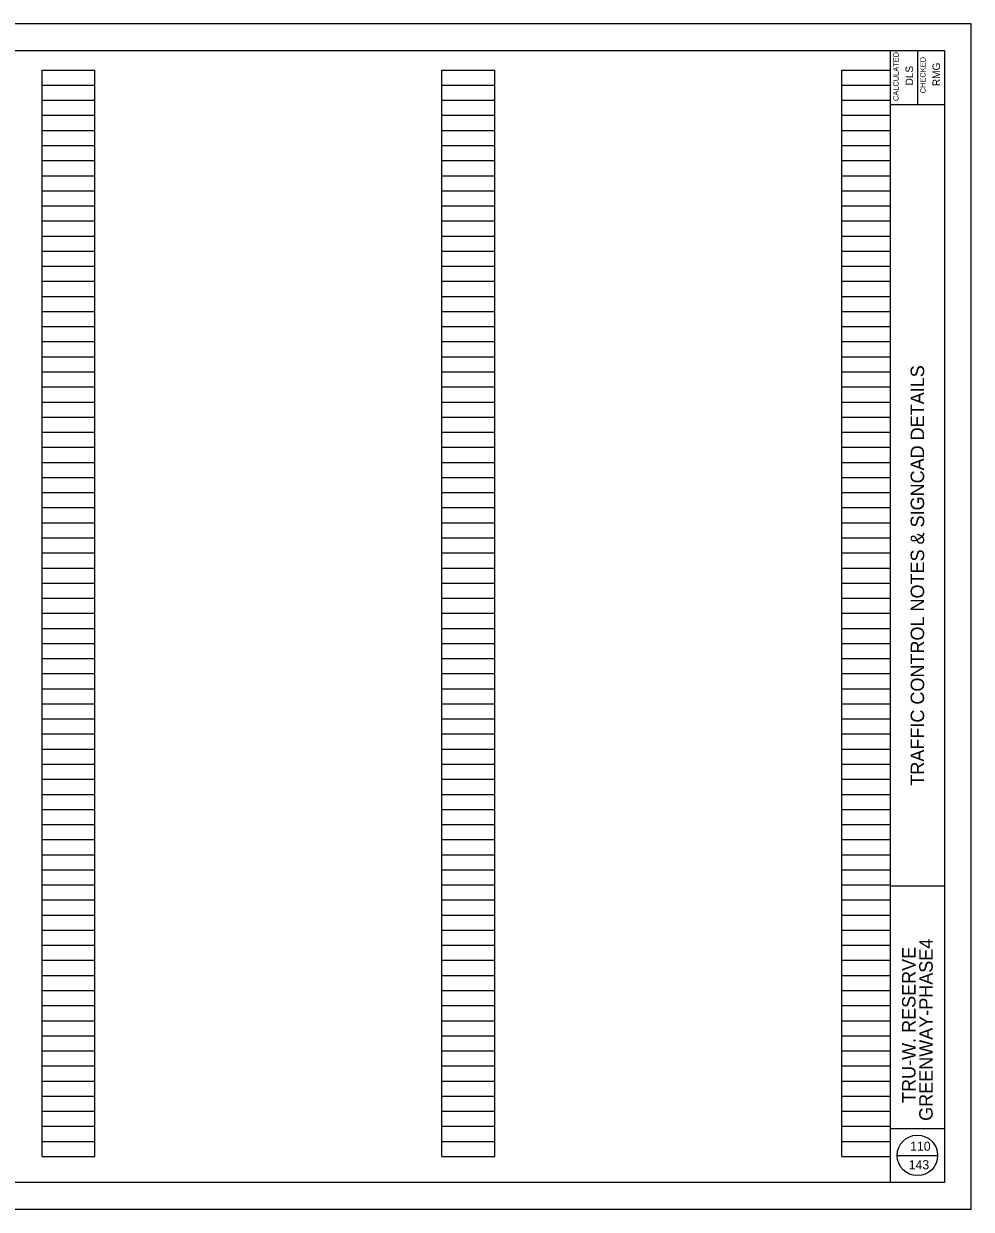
# Model space of a CAD drawing. Extents: x -16.4 to 17.6, y -12.9 to 9.1.
# Drawn here: x 0.05 to 17.63, y -12.91 to 9.09 of the extents above; entities that cross this region are included whole.
import ezdxf

# ---------------------------------------------------------------- set-up
doc = ezdxf.new("R2010")
doc.units = 0
for name, color, linetype in [('SC_Scratch1', 7, 'Continuous'), ('SH_Border', 7, 'Continuous'), ('SH_Cut_Line', 7, 'Continuous'), ('SH_Data', 7, 'Continuous')]:
    doc.layers.add(name, color=color, linetype=linetype)

msp = doc.modelspace()

# ---------------------------------------------------------------- linework, layer by layer
at = {"layer": 'SC_Scratch1'}
for p, q in [((0.389, -11.927), (0.389, 8.233)), ((0.389, 8.233), (1.369, 8.233)), ((1.369, -11.927), (1.369, 8.233)), ((7.809, -11.927), (7.809, 8.233)), ((7.809, 8.233), (8.789, 8.233)), ((8.789, -11.927), (8.789, 8.233)), ((15.229, -11.927), (15.229, 8.233)), ((15.229, 8.233), (16.129, 8.233)), ((16.129, -11.927), (16.129, 8.233)), ((0.389, 7.953), (1.369, 7.953)), ((7.809, 7.953), (8.789, 7.953)), ((15.229, 7.953), (16.129, 7.953)), ((0.389, 7.673), (1.369, 7.673)), ((7.809, 7.673), (8.789, 7.673)), ((15.229, 7.673), (16.129, 7.673)), ((0.389, 7.393), (1.369, 7.393)), ((7.809, 7.393), (8.789, 7.393)), ((15.229, 7.393), (16.129, 7.393)), ((0.389, 7.113), (1.369, 7.113)), ((7.809, 7.113), (8.789, 7.113)), ((15.229, 7.113), (16.129, 7.113)), ((0.389, 6.833), (1.369, 6.833)), ((7.809, 6.833), (8.789, 6.833)), ((15.229, 6.833), (16.129, 6.833)), ((0.389, 6.553), (1.369, 6.553)), ((7.809, 6.553), (8.789, 6.553)), ((15.229, 6.553), (16.129, 6.553)), ((0.389, 6.273), (1.369, 6.273)), ((7.809, 6.273), (8.789, 6.273)), ((15.229, 6.273), (16.129, 6.273)), ((0.389, 5.993), (1.369, 5.993)), ((7.809, 5.993), (8.789, 5.993)), ((15.229, 5.993), (16.129, 5.993)), ((0.389, 5.713), (1.369, 5.713)), ((7.809, 5.713), (8.789, 5.713)), ((15.229, 5.713), (16.129, 5.713)), ((0.389, 5.433), (1.369, 5.433)), ((7.809, 5.433), (8.789, 5.433)), ((15.229, 5.433), (16.129, 5.433)), ((0.389, 5.153), (1.369, 5.153)), ((7.809, 5.153), (8.789, 5.153)), ((15.229, 5.153), (16.129, 5.153)), ((0.389, 4.873), (1.369, 4.873)), ((7.809, 4.873), (8.789, 4.873)), ((15.229, 4.873), (16.129, 4.873)), ((0.389, 4.593), (1.369, 4.593)), ((7.809, 4.593), (8.789, 4.593)), ((15.229, 4.593), (16.129, 4.593)), ((0.389, 4.313), (1.369, 4.313)), ((7.809, 4.313), (8.789, 4.313)), ((15.229, 4.313), (16.129, 4.313)), ((0.389, 4.033), (1.369, 4.033)), ((7.809, 4.033), (8.789, 4.033)), ((15.229, 4.033), (16.129, 4.033)), ((0.389, 3.753), (1.369, 3.753)), ((7.809, 3.753), (8.789, 3.753)), ((15.229, 3.753), (16.129, 3.753)), ((0.389, 3.473), (1.369, 3.473)), ((7.809, 3.473), (8.789, 3.473)), ((15.229, 3.473), (16.129, 3.473)), ((0.389, 3.193), (1.369, 3.193)), ((7.809, 3.193), (8.789, 3.193)), ((15.229, 3.193), (16.129, 3.193)), ((0.389, 2.913), (1.369, 2.913)), ((7.809, 2.913), (8.789, 2.913)), ((15.229, 2.913), (16.129, 2.913)), ((0.389, 2.633), (1.369, 2.633)), ((7.809, 2.633), (8.789, 2.633)), ((15.229, 2.633), (16.129, 2.633)), ((0.389, 2.353), (1.369, 2.353)), ((7.809, 2.353), (8.789, 2.353)), ((15.229, 2.353), (16.129, 2.353)), ((0.389, 2.073), (1.369, 2.073)), ((7.809, 2.073), (8.789, 2.073)), ((15.229, 2.073), (16.129, 2.073)), ((0.389, 1.793), (1.369, 1.793)), ((7.809, 1.793), (8.789, 1.793)), ((15.229, 1.793), (16.129, 1.793)), ((0.389, 1.513), (1.369, 1.513)), ((7.809, 1.513), (8.789, 1.513)), ((15.229, 1.513), (16.129, 1.513)), ((0.389, 1.233), (1.369, 1.233)), ((7.809, 1.233), (8.789, 1.233)), ((15.229, 1.233), (16.129, 1.233)), ((0.389, 0.953), (1.369, 0.953)), ((7.809, 0.953), (8.789, 0.953)), ((15.229, 0.953), (16.129, 0.953)), ((0.389, 0.673), (1.369, 0.673)), ((7.809, 0.673), (8.789, 0.673)), ((15.229, 0.673), (16.129, 0.673)), ((0.389, 0.393), (1.369, 0.393)), ((7.809, 0.393), (8.789, 0.393)), ((15.229, 0.393), (16.129, 0.393)), ((0.389, 0.113), (1.369, 0.113)), ((7.809, 0.113), (8.789, 0.113)), ((15.229, 0.113), (16.129, 0.113)), ((0.389, -0.167), (1.369, -0.167)), ((7.809, -0.167), (8.789, -0.167)), ((15.229, -0.167), (16.129, -0.167)), ((0.389, -0.447), (1.369, -0.447)), ((7.809, -0.447), (8.789, -0.447)), ((15.229, -0.447), (16.129, -0.447)), ((0.389, -0.727), (1.369, -0.727)), ((7.809, -0.727), (8.789, -0.727)), ((15.229, -0.727), (16.129, -0.727)), ((0.389, -1.007), (1.369, -1.007)), ((7.809, -1.007), (8.789, -1.007)), ((15.229, -1.007), (16.129, -1.007)), ((0.389, -1.287), (1.369, -1.287)), ((7.809, -1.287), (8.789, -1.287)), ((15.229, -1.287), (16.129, -1.287)), ((0.389, -1.567), (1.369, -1.567)), ((7.809, -1.567), (8.789, -1.567)), ((15.229, -1.567), (16.129, -1.567)), ((0.389, -1.847), (1.369, -1.847)), ((7.809, -1.847), (8.789, -1.847)), ((15.229, -1.847), (16.129, -1.847)), ((0.389, -2.127), (1.369, -2.127)), ((7.809, -2.127), (8.789, -2.127)), ((15.229, -2.127), (16.129, -2.127)), ((0.389, -2.407), (1.369, -2.407)), ((7.809, -2.407), (8.789, -2.407)), ((15.229, -2.407), (16.129, -2.407)), ((0.389, -2.687), (1.369, -2.687)), ((7.809, -2.687), (8.789, -2.687)), ((15.229, -2.687), (16.129, -2.687)), ((0.389, -2.967), (1.369, -2.967)), ((7.809, -2.967), (8.789, -2.967)), ((15.229, -2.967), (16.129, -2.967)), ((0.389, -3.247), (1.369, -3.247)), ((7.809, -3.247), (8.789, -3.247)), ((15.229, -3.247), (16.129, -3.247)), ((0.389, -3.527), (1.369, -3.527)), ((7.809, -3.527), (8.789, -3.527)), ((15.229, -3.527), (16.129, -3.527)), ((0.389, -3.807), (1.369, -3.807)), ((7.809, -3.807), (8.789, -3.807)), ((15.229, -3.807), (16.129, -3.807)), ((0.389, -4.087), (1.369, -4.087)), ((7.809, -4.087), (8.789, -4.087)), ((15.229, -4.087), (16.129, -4.087)), ((0.389, -4.367), (1.369, -4.367)), ((7.809, -4.367), (8.789, -4.367)), ((15.229, -4.367), (16.129, -4.367)), ((0.389, -4.647), (1.369, -4.647)), ((7.809, -4.647), (8.789, -4.647)), ((15.229, -4.647), (16.129, -4.647)), ((0.389, -4.927), (1.369, -4.927)), ((7.809, -4.927), (8.789, -4.927)), ((15.229, -4.927), (16.129, -4.927)), ((0.389, -5.207), (1.369, -5.207)), ((7.809, -5.207), (8.789, -5.207)), ((15.229, -5.207), (16.129, -5.207)), ((0.389, -5.487), (1.369, -5.487)), ((7.809, -5.487), (8.789, -5.487)), ((15.229, -5.487), (16.129, -5.487)), ((0.389, -5.767), (1.369, -5.767)), ((7.809, -5.767), (8.789, -5.767)), ((15.229, -5.767), (16.129, -5.767)), ((0.389, -6.047), (1.369, -6.047)), ((7.809, -6.047), (8.789, -6.047)), ((15.229, -6.047), (16.129, -6.047)), ((0.389, -6.327), (1.369, -6.327)), ((7.809, -6.327), (8.789, -6.327)), ((15.229, -6.327), (16.129, -6.327)), ((0.389, -6.607), (1.369, -6.607)), ((7.809, -6.607), (8.789, -6.607)), ((15.229, -6.607), (16.129, -6.607)), ((0.389, -6.887), (1.369, -6.887)), ((7.809, -6.887), (8.789, -6.887)), ((15.229, -6.887), (16.129, -6.887)), ((0.389, -7.167), (1.369, -7.167)), ((7.809, -7.167), (8.789, -7.167)), ((15.229, -7.167), (16.129, -7.167)), ((0.389, -7.447), (1.369, -7.447)), ((7.809, -7.447), (8.789, -7.447)), ((15.229, -7.447), (16.129, -7.447)), ((0.389, -7.727), (1.369, -7.727)), ((7.809, -7.727), (8.789, -7.727)), ((15.229, -7.727), (16.129, -7.727)), ((0.389, -8.007), (1.369, -8.007)), ((7.809, -8.007), (8.789, -8.007)), ((15.229, -8.007), (16.129, -8.007)), ((0.389, -8.287), (1.369, -8.287)), ((7.809, -8.287), (8.789, -8.287)), ((15.229, -8.287), (16.129, -8.287)), ((0.389, -8.567), (1.369, -8.567)), ((7.809, -8.567), (8.789, -8.567)), ((15.229, -8.567), (16.129, -8.567)), ((0.389, -8.847), (1.369, -8.847)), ((7.809, -8.847), (8.789, -8.847)), ((15.229, -8.847), (16.129, -8.847)), ((0.389, -9.127), (1.369, -9.127)), ((7.809, -9.127), (8.789, -9.127)), ((15.229, -9.127), (16.129, -9.127)), ((0.389, -9.407), (1.369, -9.407)), ((7.809, -9.407), (8.789, -9.407)), ((15.229, -9.407), (16.129, -9.407)), ((0.389, -9.687), (1.369, -9.687)), ((7.809, -9.687), (8.789, -9.687)), ((15.229, -9.687), (16.129, -9.687)), ((0.389, -9.967), (1.369, -9.967)), ((7.809, -9.967), (8.789, -9.967)), ((15.229, -9.967), (16.129, -9.967)), ((0.389, -10.247), (1.369, -10.247)), ((7.809, -10.247), (8.789, -10.247)), ((15.229, -10.247), (16.129, -10.247)), ((0.389, -10.527), (1.369, -10.527)), ((7.809, -10.527), (8.789, -10.527)), ((15.229, -10.527), (16.129, -10.527)), ((0.389, -10.807), (1.369, -10.807)), ((7.809, -10.807), (8.789, -10.807)), ((15.229, -10.807), (16.129, -10.807)), ((0.389, -11.087), (1.369, -11.087)), ((7.809, -11.087), (8.789, -11.087)), ((15.229, -11.087), (16.129, -11.087)), ((0.389, -11.367), (1.369, -11.367)), ((7.809, -11.367), (8.789, -11.367)), ((15.229, -11.367), (16.129, -11.367)), ((0.389, -11.647), (1.369, -11.647)), ((7.809, -11.647), (8.789, -11.647)), ((15.229, -11.647), (16.129, -11.647)), ((0.389, -11.927), (1.369, -11.927)), ((7.809, -11.927), (8.789, -11.927)), ((15.229, -11.927), (16.129, -11.927))]:
    msp.add_line(p, q, dxfattribs=at)
at = {"layer": 'SH_Border'}
for p, q in [((16.129, -12.407), (16.129, 8.593)), ((16.629, 8.593), (16.629, 7.593)), ((16.129, 7.593), (17.129, 7.593)), ((16.129, -6.907), (17.129, -6.907)), ((16.129, -11.407), (17.129, -11.407))]:
    msp.add_line(p, q, dxfattribs=at)
msp.add_lwpolyline([(-14.371, 8.593), (17.129, 8.593), (17.129, -12.407), (-14.371, -12.407)], close=True, dxfattribs=at)
at = {"layer": 'SH_Cut_Line'}
msp.add_lwpolyline([(-16.371, -12.907), (17.629, -12.907), (17.629, 9.093), (-16.371, 9.093)], close=True, dxfattribs=at)
at = {"layer": 'SH_Data'}
msp.add_line((16.254, -11.907), (17.004, -11.907), dxfattribs=at)
msp.add_circle((16.629, -11.907), 0.375, dxfattribs=at)

# ---------------------------------------------------------------- texts
for s, height, p in [('CALCULATED', 0.1, (16.281, 7.658)), ('CHECKED', 0.1, (16.781, 7.801)), ('DLS', 0.14, (16.549, 7.946)), ('RMG', 0.14, (17.049, 7.935)), ('TRAFFIC CONTROL NOTES & SIGNCAD DETAILS', 0.25, (16.754, -5.046)), ('GREENWAY-PHASE4', 0.25, (16.913, -11.266)), ('TRU-W. RESERVE', 0.25, (16.594, -10.934))]:
    msp.add_text(s, height=height, rotation=90, dxfattribs=at).set_placement(p)
for s, p in [('110', (16.495, -11.822)), ('143', (16.468, -12.166))]:
    msp.add_text(s, height=0.17, dxfattribs=at).set_placement(p)

doc.saveas('drawing.dxf')
